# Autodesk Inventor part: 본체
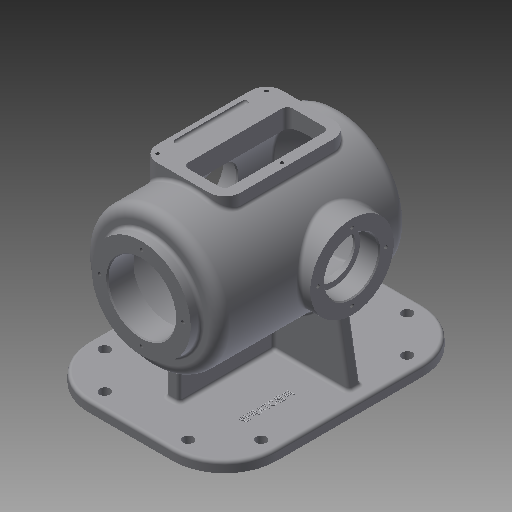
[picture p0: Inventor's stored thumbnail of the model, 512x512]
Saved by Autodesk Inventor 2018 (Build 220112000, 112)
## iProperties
Created: 2016-02
Part Number: 본체
Material: 일반
Document SubType Name: Modeling
Designer: mduedu
Density: 2.71 g/cm^3
Appearance: 기본값
Author: mduedu
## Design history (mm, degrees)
sketch "스케치2"
  geometry: L1 (0, 100)-(0, -100); L2 (65, -75.993)-(65, 100); L3 (65, 100)-(0, 100); A1 r 100 centre (0, 0) between (0, -100) and (65, -75.993); 2 further points
  constraints: 6 end point, 2 midpoint, 2 point on circle, 1 centre point, 1 coincident, 1 horizontal, 1 parallel, 1 vertical
  dimensions: "d3" = 200 distance of L1.start L1.end; "d5" = 130 diameter of L2 L1; "d6" = 100 radius of A1
revolve "회전1" sketch "스케치2" stored, may be unused: angle "d7" = 90 deg
sketch "스케치3"
  geometry: C1 r 47.5 at (0, 0); 1 further point
  constraints: 1 centre point, 1 coincident
  dimensions: "d8" = 95 diameter of C1
extrude "돌출2" join sketch "스케치3" distance "d10" = 10; taper "d11" = 0 deg
sketch "스케치5"
  geometry: L1 (47.5, 110)-(47.5, 100) reference; L2 (47.5, 100)-(65, 100) reference; L3 (65, 100)-(65, -75.993) reference; L4 (-65, -75.993)-(-65, 100) reference; L5 (-65, 100)-(-47.5, 100) reference; L6 (-47.5, 100)-(-47.5, 110) reference; L7 (-47.5, 110)-(47.5, 110) reference; L8 (55, 85)-(55, -71.239); L9 (0, 85)-(55, 85); L10 (0, 85)-(0, -90); A1 r 100 centre (0, 0) between (0, -100) and (65, -75.993) reference; A2 r 100 centre (0, 0) between (-65, -75.993) and (0, -100) reference; A3 r 90 centre (0, 0) between (0, -90) and (55, -71.239); 1 further point
  constraints: 6 end point, 2 point on circle, 1 centre point, 1 parallel, 1 perpendicular, 1 point on line, 1 vertical
  dimensions: "d13" = 10 distance between parallel lines of L3 L8; "d14" = 10 radial gap between concentric circles of A3 A1; "d15" = 15 distance between parallel lines of L9 L2
revolve "회전2" sketch "스케치5" stored, may be unused: angle "d16" = 90 deg
hole "구멍1" diameter "d19" = 65; stored, may be unused: countersink angle "d23" = 90 deg, drill point angle "d25" = 118 deg; dims "d17" = 10, "d18" = 10, "d20" = 6, "d21" = 4, "d22" = 2, "d24" = 8
node "작업 평면1"
sketch "스케치6"
  geometry: L1 (47.5, 110)-(-47.5, 110) reference; C1 r 40 at (0, -17); 1 further point
  constraints: 1 centre point, 1 vertical alignment
  dimensions: "d27" = 80 diameter of C1; "d29" = 127 distance from line of C1.centre L1
extrude "돌출3" join sketch "스케치6" stored distance "d30" = 10; taper "d31" = 0 deg
hole "구멍2" diameter "d34" = 42; stored, may be unused: countersink angle "d38" = 90 deg, drill point angle "d40" = 118 deg; dims "d32" = 10, "d33" = 10, "d35" = 6, "d36" = 52, "d37" = 18, "d39" = 8
sketch "스케치7" dims "d41" = 65
  geometry: C1 r 40 at (0, 0) reference; 3 further points
  constraints: 2 vertical alignment, 1 coincident, 2 other
hole "구멍3" sketch "스케치7" at (0, 32.5) diameter "d43" = 3.242; stored, may be unused: countersink angle "d47" = 90 deg, drill point angle "d49" = 118 deg; dims "d44" = 11, "d45" = 13, "d46" = 18, "d48" = 13
sketch "스케치8" dims "d53" = 80
  geometry: 3 further points
  constraints: 2 vertical alignment, 1 coincident, 2 other
hole "구멍4" sketch "스케치8" at (0, 40) diameter "d56" = 3.242; stored, may be unused: countersink angle "d60" = 90 deg, drill point angle "d62" = 118 deg; dims "d57" = 11, "d58" = 13, "d59" = 18, "d61" = 13
fillet "모깎기1" dims "d66" = 10
fillet "모깎기2" dims "d67" = 3
fillet "모깎기3" dims "d68" = 0.3
chamfer "모따기1" distance "d69" = 1; stored, may be unused: second distance "d70" = 2, angle "d71" = 45 deg
node "작업 평면5"
sketch "스케치23"
  geometry: L1 (6, 80)-(-6, 80); L2 (-6, 80)-(-6, -60); L3 (-6, -60)-(6, -60); L4 (6, -60)-(6, 80); L5 (-55, 100)-(55, 100) reference; 2 further points
  constraints: 8 end point, 2 parallel, 1 horizontal, 1 midpoint, 1 perpendicular, 1 vertical alignment
  dimensions: "d177" = 12 distance of L1.start L1.end; "d179" = 140 distance of L3.end L1.start; "d180" = 20 distance between parallel lines of L1 L5
extrude "돌출14" join sketch "스케치23" stored distance "d181" = 10; taper "d182" = 0 deg
node "작업 평면6"
sketch "스케치15"
  geometry: L1 (-30, 60)-(50, 60); L2 (50, 60)-(50, -60); L3 (50, -60)-(-30, -60); L4 (-30, -60)-(-30, 60); 3 further points
  constraints: 8 end point, 2 parallel, 1 horizontal, 1 horizontal alignment, 1 midpoint, 1 perpendicular, 1 vertical alignment
  dimensions: "d110" = 80 distance of L2.end L3.end; "d112" = 60 distance from line of L3 point (10, 0); "d113" = 120 distance of L1.end L2.end; "d149" = 30 distance from line of L4 point (0, 0)
extrude "돌출8" join sketch "스케치15" stored distance "d114" = 10; taper "d115" = 0 deg
fillet "모깎기7" dims "d116" = 15
sketch "스케치16"
  geometry: L1 (-30, -45)-(-30, 45) reference; L2 (-15, 60)-(35, 60) reference; L3 (35, -60)-(-15, -60) reference; L4 (-20, -45)-(-20, 45); L5 (-15, 50)-(15, 50); L6 (20, 45)-(20, -45); L7 (15, -50)-(-15, -50); L8 (50, 45)-(50, -45) reference; A1 r 15 centre (-15, -45) between (-30, -45) and (-15, -60) reference; A2 r 15 centre (-15, 45) between (-15, 60) and (-30, 45) reference; A3 r 5 centre (-15, -45) between (-20, -45) and (-15, -50); A4 r 5 centre (-15, 45) between (-15, 50) and (-20, 45); A5 r 5 centre (15, 45) between (20, 45) and (15, 50); A6 r 5 centre (15, -45) between (15, -50) and (20, -45); A7 r 15 centre (35, 45) between (50, 45) and (35, 60) reference; A8 r 15 centre (35, -45) between (35, -60) and (50, -45) reference
  constraints: 8 end point, 8 point on circle, 4 centre point, 2 equal radius, 3 other
  dimensions: "d137" = 10 distance between parallel lines of L4 L1; "d150" = 40 distance between parallel lines of L6 L4; "d151" = 100 distance between parallel lines of L7 L5
extrude "돌출9" cut sketch "스케치16" stored distance "d118" = 10; taper "d119" = 0 deg
fillet "모깎기8" dims "d120" = 3
sketch "스케치17"
  geometry: L1 (-30, -45)-(-30, 45) reference; L2 (-20, 45)-(-20, -45) reference; L3 (-15, -50)-(15, -50) reference; L4 (20, -45)-(20, 45) reference; L5 (15, 50)-(-15, 50) reference; L6 (-15, 60)-(35, 60) reference; L7 (35, -60)-(-15, -60) reference; L8 (15, 55)-(-15, 55); L9 (-25, 45)-(-25, -45); L10 (-15, -55)-(15, -55); L11 (25, -45)-(25, 45); L12 (50, 45)-(50, -45) reference; L13 (35, 55)-(-15, 55); L14 (-25, 45)-(-25, -45); L15 (-15, -55)-(35, -55); L16 (45, -45)-(45, 45); A1 r 5 centre (-15, 45) between (-15, 50) and (-20, 45) reference; A2 r 5 centre (-15, -45) between (-20, -45) and (-15, -50) reference; A3 r 5 centre (15, -45) between (15, -50) and (20, -45) reference; A4 r 5 centre (15, 45) between (20, 45) and (15, 50) reference; A5 r 15 centre (-15, 45) between (-15, 60) and (-30, 45) reference; A6 r 15 centre (-15, -45) between (-30, -45) and (-15, -60) reference; A7 r 10 centre (-15, 45) between (-15, 55) and (-25, 45); A8 r 10 centre (-15, -45) between (-25, -45) and (-15, -55); A9 r 10 centre (15, -45) between (15, -55) and (25, -45); A10 r 10 centre (15, 45) between (25, 45) and (15, 55); A11 r 15 centre (35, 45) between (50, 45) and (35, 60) reference; A12 r 15 centre (35, -45) between (35, -60) and (50, -45) reference; A13 r 10 centre (-15, 45) between (-15, 55) and (-25, 45); A14 r 10 centre (-15, -45) between (-25, -45) and (-15, -55); A15 r 10 centre (35, -45) between (35, -55) and (45, -45); A16 r 10 centre (35, 45) between (45, 45) and (35, 55); 6 further points
  constraints: 18 point on circle, 16 end point, 8 centre point, 4 midpoint, 4 tangent, 11 other
  dimensions: "d138" = 5 distance between parallel lines of L8 L6; "d157" = 5 distance between parallel lines of L12 L16
hole "구멍5" sketch "스케치17" at (-25, 0), (42.071, 52.071), (42.071, -52.071) diameter "d122" = 3.242; stored, may be unused: countersink angle "d126" = 90 deg, drill point angle "d128" = 118 deg; dims "d123" = 9, "d124" = 13, "d125" = 18, "d127" = 11
sketch "스케치19"
  geometry: L1 (-50, 70)-(-35, 70) reference; L2 (-50, 42.603)-(-50, 70) reference; C1 r 2.5 at (-43, 70); 1 further point
  constraints: 1 centre point, 1 point on line
  dimensions: "d152" = 5 diameter of C1; "d153" = 7 distance from line of C1.centre L2
extrude "돌출11" cut sketch "스케치19" stored distance "d154" = 70; taper "d155" = 0 deg
fillet "모깎기11" dims "d156" = 2.5
sketch "스케치20"
  geometry: L1 (-90, 120)-(90, 120); L2 (90, 120)-(90, -120); L3 (90, -120)-(-90, -120); L4 (-90, -120)-(-90, 120); 3 further points
  constraints: 8 end point, 2 parallel, 2 vertical alignment, 1 coincident, 1 horizontal, 1 midpoint, 1 perpendicular
  dimensions: "d162" = 180 distance of L1.start L1.end; "d164" = 240 distance of L1.end L2.end; "d165" = 120 distance from line of L1 point (0, 0)
extrude "돌출12" join sketch "스케치20" distance "d166" = 10; taper "d167" = 0 deg
fillet "모깎기12" dims "d168" = 50
node "작업 평면8"
  node "작업축1"
sketch "스케치24"
  geometry: L1 (128, 34.121)-(127.026, 32.5) reference; L2 (127.026, 32.5)-(128, 30.879) reference; L3 (128, 30.879)-(141, 30.879) reference; L4 (141, 30.879)-(141, 27) reference; L5 (141, 27)-(140, 26) reference; L6 (140, 26)-(123.3, 26) reference; L7 (123, 25.7)-(123, 21) reference; L8 (123, 21)-(116.833, 21) reference; L9 (86, 51.235)-(86, 70) reference; L10 (86, 70)-(106.5, 70) reference; L11 (111.5, 70)-(116, 70) reference; L12 (116, 70)-(116, 42.603) reference; L13 (118.678, 40)-(141, 40) reference; L14 (141, 40)-(141, 34.121) reference; L15 (141, 34.121)-(128, 34.121) reference; L16 (4, -34.121)-(4.974, -32.5) reference; L17 (4.974, -32.5)-(4, -30.879) reference; L18 (4, -30.879)-(-9, -30.879) reference; L19 (-9, -30.879)-(-9, -27) reference; L20 (-9, -27)-(-8, -26) reference; L21 (-8, -26)-(8.7, -26) reference; L22 (9, -25.7)-(9, -21) reference; L23 (9, -21)-(15.167, -21) reference; L24 (116.833, -21)-(123, -21) reference; L25 (123, -21)-(123, -25.7) reference; L26 (123.3, -26)-(140, -26) reference; L27 (140, -26)-(141, -27) reference; L28 (141, -27)-(141, -30.879) reference; L29 (141, -30.879)-(128, -30.879) reference; L30 (128, -30.879)-(127.026, -32.5) reference; L31 (127.026, -32.5)-(128, -34.121) reference; L32 (128, -34.121)-(141, -34.121) reference; L33 (141, -34.121)-(141, -40) reference; L34 (141, -40)-(118.678, -40) reference; L35 (72, -64.722)-(72, -100) reference; L36 (72, -100)-(156, -100) reference; L37 (156, -100)-(156, -110) reference; L38 (156, -110)-(-24, -110) reference; L39 (-24, -110)-(-24, -100) reference; L40 (-24, -100)-(60, -100) reference; L41 (60, -100)-(60, -64.722) reference; L42 (13.322, -40)-(-9, -40) reference; L43 (-9, -40)-(-9, -34.121) reference; L44 (-9, -34.121)-(4, -34.121) reference; L45 (4.974, 32.5)-(4, 34.121) reference; L46 (4, 34.121)-(-9, 34.121) reference; L47 (-9, 34.121)-(-9, 40) reference; L48 (-9, 40)-(13.322, 40) reference; L49 (36, 59.456)-(36, 70) reference; L50 (36, 70)-(46, 70) reference; L51 (46, 70)-(46, 51.235) reference; L52 (15.167, 21)-(9, 21) reference; L53 (9, 21)-(9, 25.7) reference; L54 (8.7, 26)-(-8, 26) reference; L55 (-8, 26)-(-9, 27) reference; L56 (-9, 27)-(-9, 30.879) reference; L57 (-9, 30.879)-(4, 30.879) reference; L58 (4, 30.879)-(4.974, 32.5) reference; L59 (-1, -40)-(-11.58, -100); A1 r 0.3 centre (123.3, 25.7) between (123.3, 26) and (123, 25.7) reference; A2 r 55 centre (66, 0) between (116.833, 21) and (86, 51.235) reference; A3 r 2.5 centre (109, 70) between (106.5, 70) and (111.5, 70) reference; A4 r 3 centre (119, 42.603) between (116, 42.603) and (116.516, 40.92) reference; A5 r 0.3 centre (8.7, -25.7) between (8.7, -26) and (9, -25.7) reference; A6 r 55 centre (66, 0) between (15.167, -21) and (116.833, -21) reference; A7 r 0.3 centre (123.3, -25.7) between (123, -25.7) and (123.3, -26) reference; A8 r 65 centre (66, 0) between (72, -64.722) and (116.354, -41.103) reference; A9 r 65 centre (66, 0) between (15.646, -41.103) and (60, -64.722) reference; A10 r 65 centre (66, 0) between (34.456, 56.833) and (15.646, 41.103) reference; A11 r 3 centre (33, 59.456) between (34.456, 56.833) and (36, 59.456) reference; A12 r 55 centre (66, 0) between (46, 51.235) and (15.167, 21) reference; A13 r 0.3 centre (8.7, 25.7) between (9, 25.7) and (8.7, 26) reference; 1 further point
  constraints: 2 end point, 2 point on line, 4 other
  dimensions: "d184" = 8 distance of L59.start L42.end; "d185" = 100 deg angle of L59 L40
feature "리브2" sketch "스케치24" dims "d186" = 1, "d187" = 12, "d188" = 0, "d189" = 0, "d190" = 1, "d191" = 1
fillet "모깎기15" dims "d192" = 3
fillet "모깎기16" dims "d193" = 3
sketch "스케치25"
  geometry: L1 (90, -70)-(90, 70) reference; L2 (40, 120)-(-40, 120) reference; L3 (-90, 70)-(-90, -70) reference; L4 (-40, -120)-(40, -120) reference; L5 (-74.004, 8)-(-9, 8) reference; L6 (-80.097, 20)-(-80.097, 14) reference; L7 (-9, 26)-(-74.004, 26) reference; L8 (-9, 57)-(-9, 26) reference; L9 (3, 63)-(-3, 63) reference; L10 (9, 26)-(9, 57) reference; L11 (74.004, 26)-(9, 26) reference; L12 (80.097, 14)-(80.097, 20) reference; L13 (9, 8)-(74.004, 8) reference; L14 (9, -77)-(9, 8) reference; L15 (-3, -83)-(3, -83) reference; L16 (-9, 8)-(-9, -77) reference; L17 (-40, 105)-(40, 105); L18 (75, 70)-(75, -70); L19 (40, -105)-(-40, -105); L20 (-75, -70)-(-75, 70); C1 r 5 at (-75, 70); C2 r 5 at (-40, 105); C3 r 5 at (40, 105); C4 r 5 at (75, 70); C5 r 5 at (75, -70); C6 r 5 at (40, -105); C7 r 5 at (-40, -105); C8 r 5 at (-75, -70); A1 r 50 centre (40, 70) between (90, 70) and (40, 120) reference; A2 r 50 centre (-40, 70) between (-40, 120) and (-90, 70) reference; A3 r 50 centre (-40, -70) between (-90, -70) and (-40, -120) reference; A4 r 50 centre (40, -70) between (40, -120) and (90, -70) reference; A5 r 6 centre (-3, 57) between (-3, 63) and (-9, 57) reference; A6 r 6 centre (3, 57) between (9, 57) and (3, 63) reference; A7 r 6 centre (3, -77) between (3, -83) and (9, -77) reference; A8 r 6 centre (-3, -77) between (-9, -77) and (-3, -83) reference; A9 r 35 centre (40, 70) between (75, 70) and (40, 105); A10 r 35 centre (40, -70) between (40, -105) and (75, -70); A11 r 35 centre (-40, -70) between (-75, -70) and (-40, -105); A12 r 35 centre (-40, 70) between (-40, 105) and (-75, 70); 5 further points; 4 other entities
  constraints: 12 centre point, 8 coincident, 8 end point, 8 point on circle, 7 equal radius, 11 other
  dimensions: "d194" = 15 distance between parallel lines of L17 L2; "d195" = 10 diameter of C1
extrude "돌출15" cut sketch "스케치25" extent not by distance; stored distance "d197" = 10; taper "d198" = 0 deg
fillet "모깎기14" dims "d170" = 3
sketch "스케치22"
  geometry: L1 (90, -70)-(90, 70) reference; 2 further points
  constraints: 1 other
  dimensions: "d174" = 40 distance from line of L1 point (50, -40); "d199" = 40 vertical distance of point (50, -40) point (0, 0)
feature "엠보싱2" sketch "스케치22" dims "d13" = 10, "d175" = 0.5, "d176" = 0
node "솔리드2"
pattern_circular "원형 패턴1" dims angle "d51" = 360 deg
mirror "대칭1"
pattern_circular "원형 패턴2" dims angle "d64" = 360 deg
mirror "대칭3"
node "투영된 루프2"
node "절단 모서리 투영1"
node "절단 모서리 투영2"
node "절단 모서리 투영3"
node "절단 모서리 투영4"
other parameters: "d26" = 75, "d183" = 0
